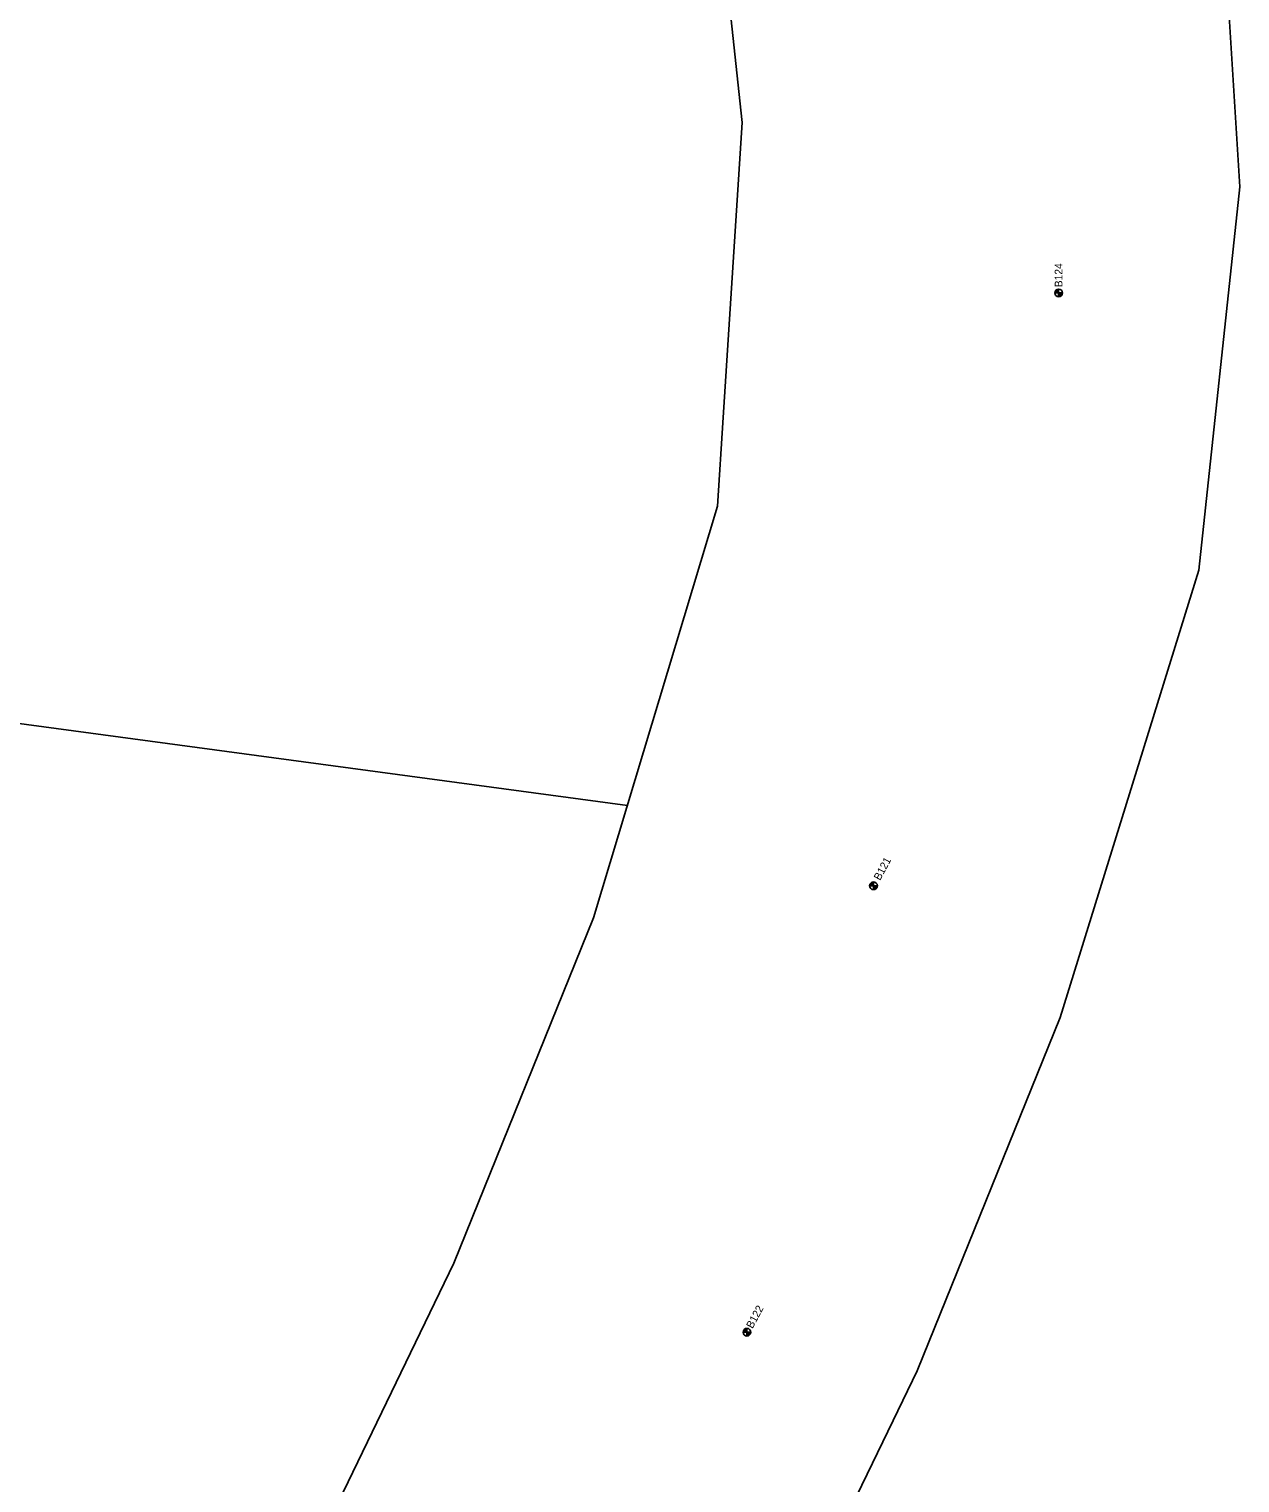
# Model space of a CAD drawing. Extents: x 345549 to 379569, y 127949 to 230467.
# Drawn here: x 355285 to 356858, y 194977 to 196864 of the extents above; entities that cross this region are included whole.
import ezdxf

# ---------------------------------------------------------------- set-up
doc = ezdxf.new("R2010")
doc.units = 0
for name, color, linetype in [('E_SOIL_BORE1 [KAPUR_CADDS_LEVELS]', 7, 'Continuous'), ('P_MARK', 7, 'Continuous'), ('P_MISC_TXT', 7, 'Continuous'), ('P_TC', 7, 'Continuous')]:
    doc.layers.add(name, color=color, linetype=linetype)

msp = doc.modelspace()

# ---------------------------------------------------------------- linework, layer by layer
at = {"layer": 'P_MARK'}
for p, q in [((356617.9, 196521.9), (356627.9, 196521.9)), ((356622.9, 196526.9), (356622.9, 196516.9)), ((356377.4, 195752), (356387.4, 195752)), ((356382.4, 195757), (356382.4, 195747)), ((356218, 195177.4), (356218, 195167.4)), ((356213, 195172.4), (356223, 195172.4))]:
    msp.add_line(p, q, dxfattribs=at)
for centre in [(356622.9, 196521.9), (356382.4, 195752), (356218, 195172.4)]:
    msp.add_circle(centre, 5, dxfattribs=at)
for centre, radius, start, end in [((356622.9, 196521.9), 4.5, 89.9869, 179.9869), ((356622.9, 196521.9), 4, 89.9869, 179.9869), ((356622.9, 196521.9), 3.5, 89.9869, 179.9869), ((356622.9, 196521.9), 3, 89.9869, 179.9869), ((356622.9, 196521.9), 2.5, 89.9869, 179.9869), ((356622.9, 196521.9), 2, 89.9869, 179.9869), ((356622.9, 196521.9), 1.5, 89.9869, 179.9869), ((356622.9, 196521.9), 1, 89.9869, 179.9869), ((356622.9, 196521.9), 0.5, 89.9869, 179.9869), ((356622.9, 196521.9), 4.5, 269.9869, 359.9869), ((356622.9, 196521.9), 4, 269.9869, 359.9869), ((356622.9, 196521.9), 3.5, 269.9869, 359.9869), ((356622.9, 196521.9), 3, 269.9869, 359.9869), ((356622.9, 196521.9), 2.5, 269.9869, 359.9869), ((356622.9, 196521.9), 2, 269.9869, 359.9869), ((356622.9, 196521.9), 1.5, 269.9869, 359.9869), ((356622.9, 196521.9), 1, 269.9869, 359.9869), ((356622.9, 196521.9), 0.5, 269.9869, 359.9869), ((356382.4, 195752), 4.5, 89.9869, 179.9869), ((356382.4, 195752), 4, 89.9869, 179.9869), ((356382.4, 195752), 3.5, 89.9869, 179.9869), ((356382.4, 195752), 3, 89.9869, 179.9869), ((356382.4, 195752), 2.5, 89.9869, 179.9869), ((356382.4, 195752), 2, 89.9869, 179.9869), ((356382.4, 195752), 1.5, 89.9869, 179.9869), ((356382.4, 195752), 1, 89.9869, 179.9869), ((356382.4, 195752), 0.5, 89.9869, 179.9869), ((356382.4, 195752), 4.5, 269.9869, 359.9869), ((356382.4, 195752), 4, 269.9869, 359.9869), ((356382.4, 195752), 3.5, 269.9869, 359.9869), ((356382.4, 195752), 3, 269.9869, 359.9869), ((356382.4, 195752), 2.5, 269.9869, 359.9869), ((356382.4, 195752), 2, 269.9869, 359.9869), ((356382.4, 195752), 1.5, 269.9869, 359.9869), ((356382.4, 195752), 1, 269.9869, 359.9869), ((356382.4, 195752), 0.5, 269.9869, 359.9869), ((356218, 195172.4), 4.5, 89.9869, 179.9869), ((356218, 195172.4), 4, 89.9869, 179.9869), ((356218, 195172.4), 3.5, 89.9869, 179.9869), ((356218, 195172.4), 3, 89.9869, 179.9869), ((356218, 195172.4), 2.5, 89.9869, 179.9869), ((356218, 195172.4), 2, 89.9869, 179.9869), ((356218, 195172.4), 1.5, 89.9869, 179.9869), ((356218, 195172.4), 1, 89.9869, 179.9869), ((356218, 195172.4), 0.5, 89.9869, 179.9869), ((356218, 195172.4), 4.5, 269.9869, 359.9869), ((356218, 195172.4), 4, 269.9869, 359.9869), ((356218, 195172.4), 3.5, 269.9869, 359.9869), ((356218, 195172.4), 3, 269.9869, 359.9869), ((356218, 195172.4), 2.5, 269.9869, 359.9869), ((356218, 195172.4), 2, 269.9869, 359.9869), ((356218, 195172.4), 1.5, 269.9869, 359.9869), ((356218, 195172.4), 1, 269.9869, 359.9869), ((356218, 195172.4), 0.5, 269.9869, 359.9869)]:
    msp.add_arc(centre, radius, start, end, dxfattribs=at)
at = {"layer": 'P_MISC_TXT'}
msp.add_line((350648.4, 196583.9), (356062.8, 195856.4), dxfattribs=at)
at = {"layer": 'P_TC'}
for points in [[(356152.8, 197292.2), (356212, 196743), (356187.3, 196360.3), (356179.9, 196244.9), (356018.8, 195710.6), (355837.4, 195262), (355656.1, 194887.8), (355482.1, 194535), (355440.2, 194457.1), (355289.7, 194177.8), (355101.7, 193774.2), (354970.8, 193454.6), (354853.6, 193071.5), (354795.4, 192718.8), (354760.1, 192236.5), (354785.6, 191878.7), (354863.4, 191037.4), (354881.9, 190789.8), (354894.4, 190621.4)], [(355623.7, 189359.8), (355599.1, 189703.9), (355561.9, 190209.7), (355523.3, 190642.3), (355513, 190780.1), (355492.2, 191058.8), (355414.4, 191899.6), (355390.9, 192230.2), (355423.4, 192673.7), (355475.5, 192990), (355581.9, 193337.5), (355704.1, 193635.9), (355884.8, 194023.7), (356075.4, 194377.7), (356076.7, 194380.4), (356252.5, 194736.8), (356408.1, 195057.9), (356439.2, 195122), (356624.7, 195580.8), (356805, 196161.9), (356858.4, 196659.7), (356825.6, 197186.3)]]:
    msp.add_lwpolyline(points, dxfattribs=at)

# ---------------------------------------------------------------- texts
at = {"layer": 'E_SOIL_BORE1 [KAPUR_CADDS_LEVELS]'}
for s, rotation, p in [('B124', 89.9869, (356627.8, 196529.2)), ('B121', 61.5935, (356390.9, 195758.2)), ('B122', 61.5935, (356225.2, 195176.3))]:
    msp.add_text(s, height=10, rotation=rotation, dxfattribs=at).set_placement(p)

doc.saveas('drawing.dxf')
